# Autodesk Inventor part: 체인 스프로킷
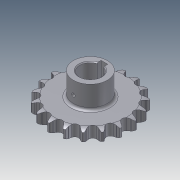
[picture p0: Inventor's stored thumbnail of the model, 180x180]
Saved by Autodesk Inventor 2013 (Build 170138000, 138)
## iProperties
Created: 2014-07
Part Number: 체인 스프로킷
Material: 강
Document SubType Name: Modeling
Designer: KYOUNG IL JANG
Density: 7.85 g/cm^3
Mass: 738.6 g
Surface Area: 236.854 cm^2
Volume: 94.0892 cm^3
CustomPartVersion: 1
Company: 한국ATC센터
Author: KYOUNG IL JANG
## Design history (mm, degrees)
sketch "이론적 톱니 프로파일"
  geometry: L1 (0, 0)-(0, 45.567); L2 (0, 0)-(14.795, 43.098); L3 (0, 45.567)-(14.795, 43.098); L4 (0, 45.567)-(5.661, 50.015); L5 (5.661, 50.015)-(-5.141, 45.406); L6 (-12.428, 43.493)-(-5.573, 46.417); L7 (-5.141, 45.406)-(-5.573, 46.417); L8 (5.573, 46.417)-(5.141, 45.406); L9 (0, 0)-(8.138, 48.771); A1 r 45.567 centre (0, 0) between (0, 45.567) and (14.795, 43.098); A2 r 49.445 centre (0, 0) between (7.302, 48.903) and (-7.302, 48.903); A3 r 4.545 centre (0, 45.567) between (-3.574, 42.758) and (3.574, 42.758); A4 r 7.453 centre (12.428, 43.493) between (7.302, 48.903) and (5.573, 46.417); A5 r 7.453 centre (-12.428, 43.493) between (-5.573, 46.417) and (-7.302, 48.903); A6 r 11.745 centre (5.661, 50.015) between (-5.141, 45.406) and (-3.574, 42.758); A7 r 11.745 centre (-5.661, 50.015) between (3.574, 42.758) and (5.141, 45.406); 2 further points
  constraints: 18 end point, 15 point on circle, 7 centre point, 3 coincident, 3 point on line, 3 symmetric about line, 3 tangent, 1 equal radius, 1 midpoint, 1 parallel, 1 vertical, 1 other
  dimensions: "d0" = 91.13301 diameter of A1 (computed from da_p, da_z); "d2" = 18.9474 deg angle of L2 L1 (computed from da_z); "d3" = 4.545 radius of A3 (= 0.5 x da_Dr + da_SC); "d10" = 128.158 deg angle of L4 L1 (computed from da_z); "d11" = 15.0526 deg angle of L5 L4 (computed from da_z); "d12" = 7.2 distance of L3.start L4.end (= 0.8 x da_Dr); "d13" = 11.745 distance of L4.end L5.end (= 1.3 x da_Dr + da_SC); "d14" = 12.6 distance of A4.centre L1.end (= 1.4 x da_Dr); "d23" = 4.5 distance from line of L9.end L3 (= da_Ha)
sketch "톱니 프로파일"
  geometry: L1 (0, 0)-(0, 45.567); L2 (0, 45.567)-(4.203, 43.837); L3 (0, 45.567)-(-4.203, 43.837); A1 r 4.545 centre (0, 45.567) between (-4.203, 43.837) and (4.203, 43.837); A2 r 22.68 centre (25.176, 35.206) between (7.12, 48.93) and (4.203, 43.837); A3 r 22.68 centre (-25.176, 35.206) between (-4.203, 43.837) and (-7.12, 48.93); A4 r 49.445 centre (0, 0) between (-7.12, 48.93) and (7.12, 48.93) reference; 1 further point
  constraints: 9 point on circle, 6 end point, 3 centre point, 2 tangent, 1 coincident, 1 equal radius, 1 vertical, 1 other
  dimensions: "d44" = 135.263 deg angle of L3 L2 (= da_Alfa); "d45" = 22.68 radius of A2 (= da_Re); "d46" = 4.545 radius of A1 (= da_Ri)
sketch "단면 프로파일"
  geometry: L1 (49.445, 0)-(-49.445, 0) reference; L2 (33.265, 6.65)-(-33.265, 6.65); L3 (-33.265, 6.65)-(-33.265, -6.65); L4 (-33.265, -6.65)-(33.265, -6.65); L5 (33.265, -6.65)-(33.265, 6.65); L6 (33.265, 6.65)-(49.445, 6.65); L7 (49.445, 6.65)-(49.445, -6.65); L8 (49.445, -6.65)-(33.265, -6.65); L9 (33.265, -6.65)-(33.265, 6.65); L10 (42.183, 6.65)-(0, 6.65); L11 (0, 6.65)-(0, -6.65); L12 (0, -6.65)-(42.183, -6.65); L13 (0, 6.65)-(0, -6.65); L14 (49.445, 4.775)-(49.445, -4.775); A1 r 15 centre (42.183, -8.35) between (49.445, 4.775) and (42.183, 6.65); A2 r 15 centre (42.183, 8.35) between (42.183, -6.65) and (49.445, -4.775); 2 further points
  constraints: 26 end point, 7 midpoint, 5 perpendicular, 4 parallel, 4 point on circle, 3 point on line, 3 symmetric about line, 2 centre point, 2 horizontal, 2 tangent, 1 collinear, 1 other
  dimensions: "d30" = 13.3 distance between parallel lines of L8 L6 (= da_Bf); "d31" = 66.53007 distance between parallel lines of L3 L5 (= da_Ds); "d32" = 13.3 distance between parallel lines of L4 L2 (= da_Bs); "d33" = 1.875 distance from line of L14.start L6 (= da_Ba); "d34" = 15 radius of A1 (= da_Rx); "d43" = 6.65 distance between parallel lines of L4 L1 (computed from da_k, da_pt, da_Bs)
revolve "슈라우드" stored, may be unused: angle "d36" = 90 deg
revolve "스트랜드" stored, may be unused: angle "d37" = 90 deg
extrude "이론적 톱니" cut sketch "이론적 톱니 프로파일" stored distance "d18" = 10; taper "d19" = 0 deg; dims "d49" = 0, "form_type" = 0 [user parameter]
extrude "톱니" cut sketch "톱니 프로파일" stored distance "d47" = 10; taper "d48" = 0 deg; dims "d50" = 10, "form_type" = 0 [user parameter]
node "타이밍 평면"
node "작업 평면3"
sketch "스케치5"
  geometry: C1 r 20 at (0, -45.567); 1 further point
  constraints: 1 centre point, 1 coincident
  dimensions: "d52" = 40 diameter of C1
extrude "돌출4" join sketch "스케치5" stored distance "d53" = 10; taper "d54" = 0 deg
sketch "스케치6"
  geometry: L1 (4, 11.843)-(4, 16.5); L2 (4, 16.5)-(-4, 16.5); L3 (-4, 16.5)-(-4, 11.843); A1 r 12.5 centre (0, 0) between (4, 11.843) and (-4, 11.843); 1 further point
  constraints: 6 end point, 2 parallel, 2 point on circle, 1 centre point, 1 coincident, 1 perpendicular, 1 vertical
  dimensions: "d55" = 25 diameter of A1; "d56" = 29 dimension on A1 L2 (computed from d55); "d57" = 8 distance of L1.end L2.end
extrude "돌출5" cut sketch "스케치6" stored distance "d58" = 10; taper "d59" = 0 deg
fillet "모깎기2" dims "d60" = 3
chamfer "모따기1" distance "d61" = 1; stored, may be unused: second distance "d62" = 2, angle "d63" = 45 deg
node "작업 평면4"
sketch "스케치7"
  geometry: L1 (-13.5, -13.3)-(13.5, -13.3) reference; 4 further points
  constraints: 1 vertical alignment
  dimensions: "d65" = 25 distance from line of point (0, 11.7) L1
hole "구멍1" sketch "스케치7" at (0, 11.7) diameter "d66" = 4.134; stored, may be unused: countersink angle "d70" = 90 deg, drill point angle "d72" = 118 deg; dims "d67" = 6, "d68" = 4, "d69" = 2, "d71" = 8
body "Solid1"
pattern_linear "스트랜드 패턴" dims "d40" = 24 (= da_pt)
pattern_circular "톱니 패턴" dims angle "d21" = 360 deg
other parameters: "da_p" = 15 [user parameter; used in 1 equation term], "da_Dr" = 9 [user parameter; used in 4 equation terms], "da_SC" = 0.045 [user parameter; used in 2 equation terms], "da_Ha" = 4.5 [user parameter; used in 1 equation term], "da_pt" = 24 [user parameter; used in 2 equation terms], "da_Bf" = 13.3 [user parameter; used in 1 equation term], "d28" = 0, "d29" = 0, "da_Ba" = 1.875 [user parameter; used in 1 equation term], "da_Rx" = 15 [user parameter; used in 1 equation term], "da_Ra" = 0.6 [user parameter], "da_Bs" = 13.3 [user parameter; used in 2 equation terms], "da_Ds" = 66.53007 [user parameter; used in 1 equation term], "d42" = 0, "da_Re" = 22.68 [user parameter; used in 1 equation term], "da_Ri" = 4.545 [user parameter; used in 1 equation term], "da_Alfa" = 135.263 deg [user parameter; used in 1 equation term]
